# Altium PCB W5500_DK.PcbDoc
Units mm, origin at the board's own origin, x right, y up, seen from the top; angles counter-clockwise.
Board outline 152.4 x 101.6 mm, 2 copper layers (Top Layer, Bottom Layer); 6 components, 71 nets, 264 pads, 61 vias.
Unrouted connection lines stored in the file: 47.
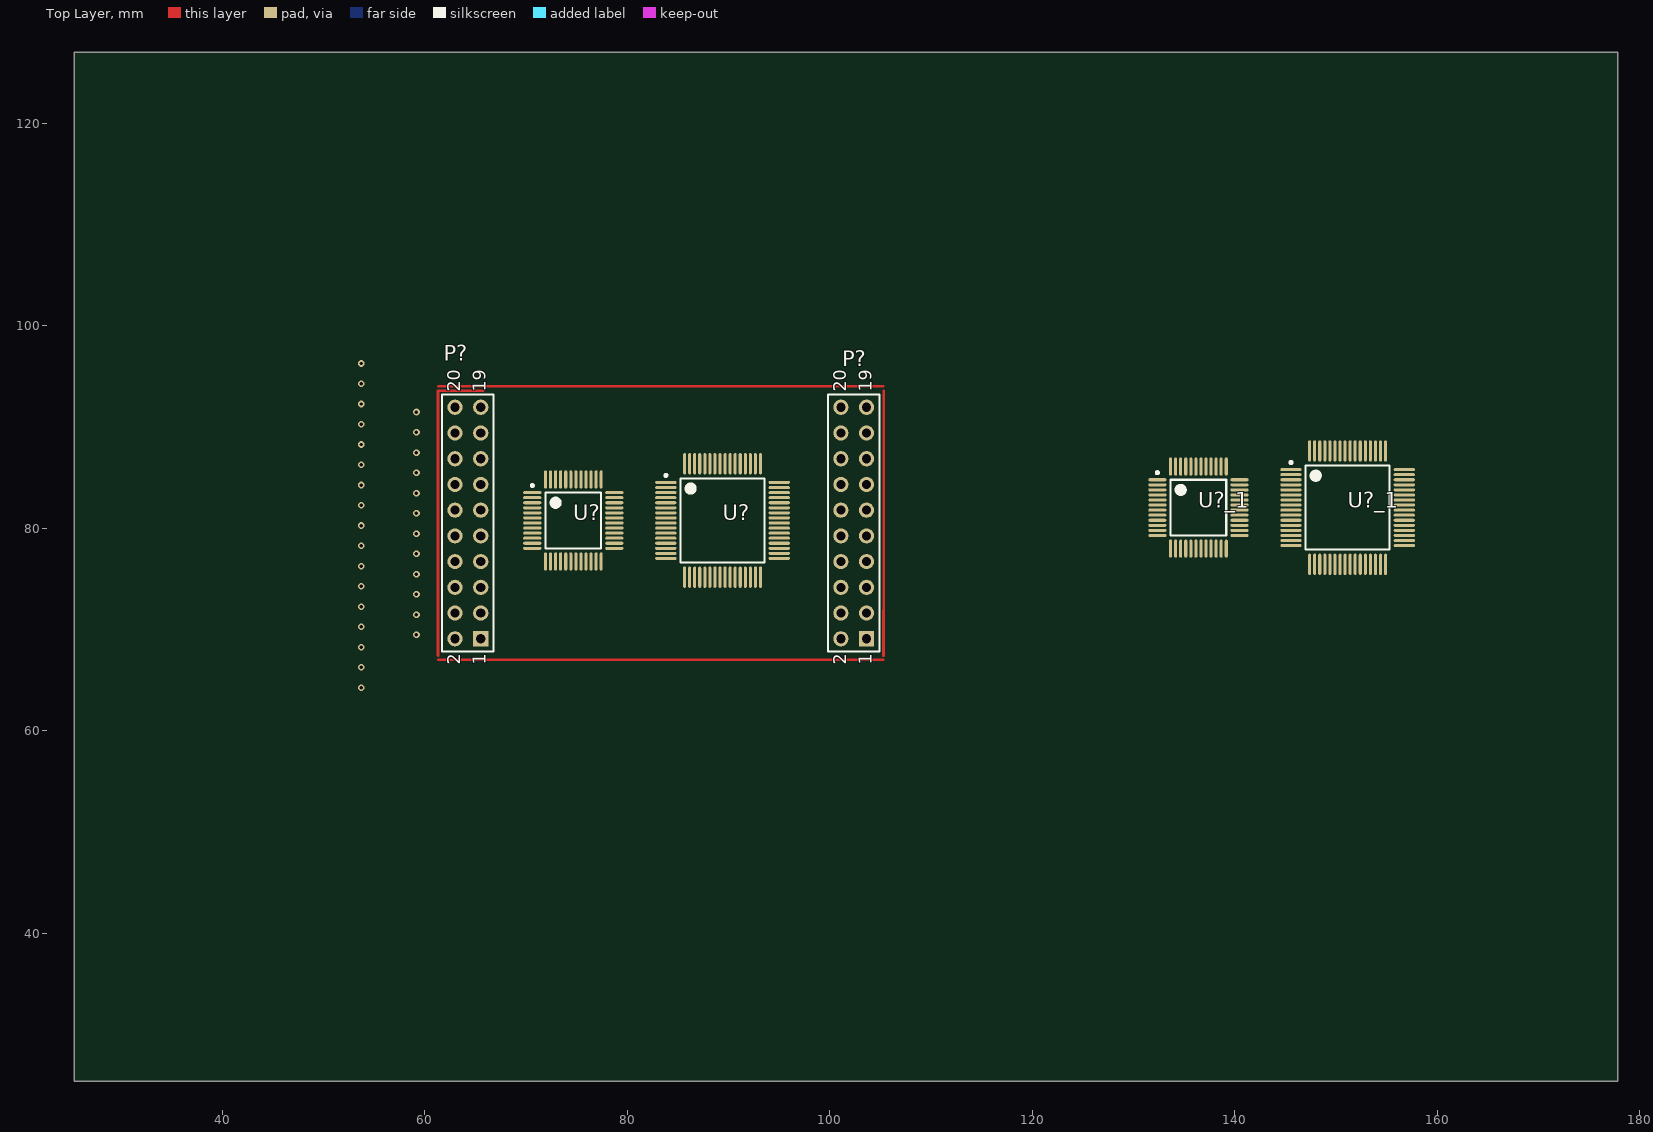
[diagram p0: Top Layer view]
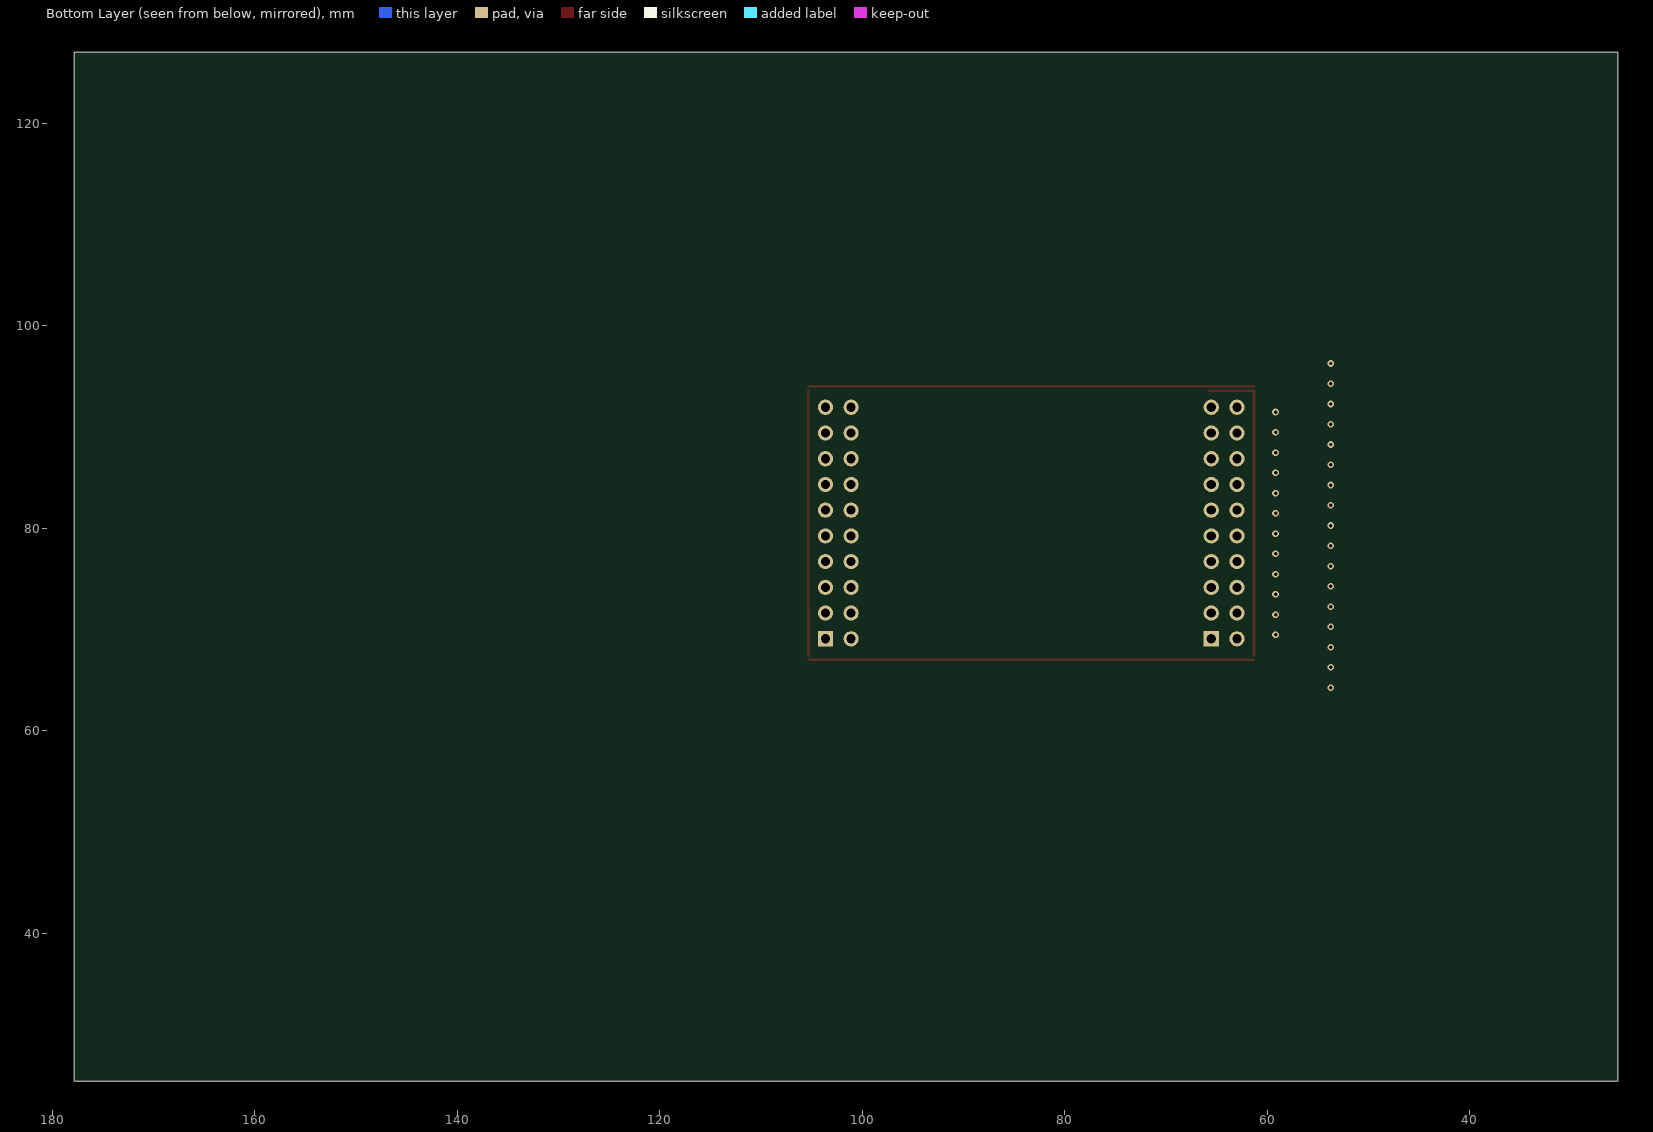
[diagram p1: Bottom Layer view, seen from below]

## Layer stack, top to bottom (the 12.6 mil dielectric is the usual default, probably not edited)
Top Layer: signal copper 0.0356
Dielectric: dielectric 0.32, FR-4, Dk 4.8
Bottom Layer: signal copper 0.0356

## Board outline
25.4,25.4 177.8,25.4 177.8,127 25.4,127

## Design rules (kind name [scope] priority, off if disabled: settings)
Clearance [All] p1: gap=0.254
PolygonConnect [All] p1: connectstyle=Relief reliefconductorwidth=0.254 reliefentries=4 polygonreliefangle="90 Angle"
RoutingVias [All] p1: holewidth=0.711 width=1.27 viastyle="Through Hole" minholewidth=0.711 minwidth=1.27 maxholewidth=0.711 maxwidth=1.27
SilkscreenOverComponentPads [All] p1: minsilkscreentomaskgap=0.254
SolderMaskExpansion [All] p1: expansion=0.102
TestPointUsage [All] p1: valid=0 allowmultiple=FALSE
Testpoint [All] p1: side=15 testpointundercomponent=TRUE minsize=1.016 maxsize=2.54 preferedsize=1.524 minholesize=0 maxholesize=1.016 preferedholesize=0.813 testpointgrid=0.025 style=1023 order=0-112345678
Width [All] p1: maxlimit=0.254 minlimit=0.254 preferedwidth=0.254
23 further rules are at their usual default settings.

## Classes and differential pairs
component class W5500+STM32: C? P? R? U? Y?

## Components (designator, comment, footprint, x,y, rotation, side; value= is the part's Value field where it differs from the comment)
P? "Header 10X2" HDR2X10 65.532,69.088 r90 top
P? "Header 10X2" HDR2X10 103.632,69.088 r90 top
U? "W5500" TQFP48_N 74.676,80.772 r0 top
U? "STM32F103RC" LQFP64_M 89.408,80.772 r0 top
U?_1 "STM32F103RC" LQFP64_M 151.13,82.042 r0 top (schematic designator U?)
U?_1 "W5500" TQFP48_N 136.398,82.042 r0 top (schematic designator U?)

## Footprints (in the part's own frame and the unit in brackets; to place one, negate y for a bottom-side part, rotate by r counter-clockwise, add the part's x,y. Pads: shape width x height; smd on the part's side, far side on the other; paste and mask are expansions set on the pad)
HDR2X10 [mm] "Connector; Header; 10x2 Position"
  rect 1.5x1.5 hole 0.9: 1(0,0)
  round 1.5 hole 0.9: 2(0,2.54) 3(2.54,0) 4(2.54,2.54) 5(5.08,0) 6(5.08,2.54) 7(7.62,0) 8(7.62,2.54) 9(10.16,0) 10(10.16,2.54) 11(12.7,0) 12(12.7,2.54) 13(15.24,0) 14(15.24,2.54) 15(17.78,0) 16(17.78,2.54) 17(20.32,0) 18(20.32,2.54) 19(22.86,0) 20(22.86,2.54)
  silkscreen extent -1.27,-1.27 24.13,3.81
LQFP64_M [mm] "Thin QFP, 64-Leads, Body 10x10mm, Pitch 0.5mm, IPC Low Density"
  oval 2.1x0.3 smd: 1(-5.6,3.75) 2(-5.6,3.25) 3(-5.6,2.75) 4(-5.6,2.25) 5(-5.6,1.75) 6(-5.6,1.25) 7(-5.6,0.75) 8(-5.6,0.25) 9(-5.6,-0.25) 10(-5.6,-0.75) 11(-5.6,-1.25) 12(-5.6,-1.75) 13(-5.6,-2.25) 14(-5.6,-2.75) 15(-5.6,-3.25) 16(-5.6,-3.75) 33(5.6,-3.75) 34(5.6,-3.25) 35(5.6,-2.75) 36(5.6,-2.25) 37(5.6,-1.75) 38(5.6,-1.25) 39(5.6,-0.75) 40(5.6,-0.25) 41(5.6,0.25) 42(5.6,0.75) 43(5.6,1.25) 44(5.6,1.75) 45(5.6,2.25) 46(5.6,2.75) 47(5.6,3.25) 48(5.6,3.75)
  oval 0.3x2.1 smd: 17(-3.75,-5.6) 18(-3.25,-5.6) 19(-2.75,-5.6) 20(-2.25,-5.6) 21(-1.75,-5.6) 22(-1.25,-5.6) 23(-0.75,-5.6) 24(-0.25,-5.6) 25(0.25,-5.6) 26(0.75,-5.6) 27(1.25,-5.6) 28(1.75,-5.6) 29(2.25,-5.6) 30(2.75,-5.6) 31(3.25,-5.6) 32(3.75,-5.6) 49(3.75,5.6) 50(3.25,5.6) 51(2.75,5.6) 52(2.25,5.6) 53(1.75,5.6) 54(1.25,5.6) 55(0.75,5.6) 56(0.25,5.6) 57(-0.25,5.6) 58(-0.75,5.6) 59(-1.25,5.6) 60(-1.75,5.6) 61(-2.25,5.6) 62(-2.75,5.6) 63(-3.25,5.6) 64(-3.75,5.6)
  silkscreen extent -5.72,-4.15 4.15,4.57, body extent -5,-5 5,5, height 1.6
TQFP48_N [mm] "Thin QFP, 48-Leads, Body 7x7mm, Pitch 0.5mm, IPC Medium Density"
  oval 1.8x0.3 smd: 1(-4.05,2.75) 2(-4.05,2.25) 3(-4.05,1.75) 4(-4.05,1.25) 5(-4.05,0.75) 6(-4.05,0.25) 7(-4.05,-0.25) 8(-4.05,-0.75) 9(-4.05,-1.25) 10(-4.05,-1.75) 11(-4.05,-2.25) 12(-4.05,-2.75) 25(4.05,-2.75) 26(4.05,-2.25) 27(4.05,-1.75) 28(4.05,-1.25) 29(4.05,-0.75) 30(4.05,-0.25) 31(4.05,0.25) 32(4.05,0.75) 33(4.05,1.25) 34(4.05,1.75) 35(4.05,2.25) 36(4.05,2.75)
  oval 0.3x1.8 smd: 13(-2.75,-4.05) 14(-2.25,-4.05) 15(-1.75,-4.05) 16(-1.25,-4.05) 17(-0.75,-4.05) 18(-0.25,-4.05) 19(0.25,-4.05) 20(0.75,-4.05) 21(1.25,-4.05) 22(1.75,-4.05) 23(2.25,-4.05) 24(2.75,-4.05) 37(2.75,4.05) 38(2.25,4.05) 39(1.75,4.05) 40(1.25,4.05) 41(0.75,4.05) 42(0.25,4.05) 43(-0.25,4.05) 44(-0.75,4.05) 45(-1.25,4.05) 46(-1.75,4.05) 47(-2.25,4.05) 48(-2.75,4.05)
  silkscreen extent -4.17,-2.75 2.75,3.57, body extent -3.5,-3.5 3.5,3.5, height 1.6

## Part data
P? P?: "Header, 10-Pin, Dual row"

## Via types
v1: diameter 0.66, hole 0.33, Top Layer to Bottom Layer, tented both sides, 61 vias

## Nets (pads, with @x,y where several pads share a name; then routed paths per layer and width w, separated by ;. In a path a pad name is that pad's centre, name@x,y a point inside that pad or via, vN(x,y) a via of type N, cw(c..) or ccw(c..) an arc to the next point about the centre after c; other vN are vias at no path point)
ACTLED: U?.27@78.726,79.022
BOOT0: 
DUPLED: U?.26@78.726,78.522
GND: U?.3@70.626,82.522 U?.9@70.626,79.522 U?.12@83.808,79.022 U?.14@72.426,76.722 U?.16@73.426,76.722 U?.18@86.158,75.172 U?.19@74.926,76.722 U?.29@78.726,80.022 U?.47@95.008,84.022 U?.48@71.926,84.822 U?.63
I2C_SCL: 
I2C_SDA: 
JTDI: U?.50
LINKLED: U?.25@78.726,78.022
NetC?_1: U?.30@78.726,80.522
NetC?_2: U?.20@75.426,76.722
NetR?_1: U?.10@70.626,79.022
NetR?_2: U?.31
NRESET: P?.16@62.992,86.868 U?.7@70.626,80.522
PA0: U?.14@83.808,78.022
PA1: 
PA2: U?.16@83.808,77.022
PA3: 
PA4: U?.20@87.158,75.172
PA5: 
PA6: U?.22@88.158,75.172
PA7: P?.5@65.532,74.168 U?.23@88.658,75.172
PA8: P?.14@62.992,84.328 U?.41@95.008,81.022
PA9: P?.12@62.992,81.788 U?.42@95.008,81.522
PA10: 
PA11: P?.8@62.992,76.708
PA12: P?.6@62.992,74.168
PA13: U?.46@95.008,83.522
PA14: U?.49
PB2/BOOT1: U?.28@78.726,79.522
PB8: U?.61
PB9: U?.62
PB10: U?.29@91.658,75.172
PB11: U?.30@92.158,75.172
PC0: 
PC1: U?.9@83.808,80.522
PC2: U?.10@83.808,80.022
PC3: 
PC4: 
PC5: P?.9@65.532,79.248 U?.25@89.658,75.172
PC7: U?.38@95.008,79.522
PC8: U?.39@95.008,80.022
PC9: U?.40@95.008,80.522
PC10: U?.51
PC11: P?.18@62.992,89.408 U?.52
PC12: U?.53
PC13: P?.13@65.532,84.328
PC14: P?.15@65.532,86.868 U?.3@83.808,83.522
PC15: P?.17@65.532,89.408
PD2: P?.11@65.532,81.788 U?.54
PD3: U?.55
PD4: U?.56
PD5: U?.57
RXN: P?.2@62.992,69.088 U?.5@83.808,82.522
RXP: P?.4@62.992,71.628 U?.6@83.808,82.022
SPDLED: U?.24
TXN: P?.1@65.532,69.088 U?.1@70.626,83.522
TXP: P?.3@65.532,71.628 U?.2
VBAT: U?.1@83.808,84.522
VCC: P?.19@65.532,91.948 P?.20@62.992,91.948 U?.13@83.808,78.522 U?.19@86.658,75.172 U?.28@91.158,75.172 U?.32@93.158,75.172 U?.48@95.008,84.522 U?.64
VCCA: P?.7@65.532,76.708 U?.4 U?.8 U?.11 U?.15 U?.17 U?.21
W5500_INTN: U?.37@77.426,84.822
W5500_MISO: 
W5500_MOSI: U?.35@78.726,83.022 U?.36@78.726,83.522
W5500_PMODE0: U?.45@73.426,84.822
W5500_PMODE1: U?.44@73.926,84.822
W5500_PMODE2: U?.43@74.426,84.822
W5500_RST: P?.10@62.992,79.248 U?.37@95.008,79.022
W5500_SCLK: U?.34@78.726,82.522
W5500_SCSN: U?.32@78.726,81.522 U?.33@78.726,82.022
XTAL_N: U?.6@70.626,81.022
XTAL_P: U?.5@70.626,81.522
pads on no net: P?.1@103.632,69.088 P?.2@101.092,69.088 P?.3@103.632,71.628 P?.4@101.092,71.628 P?.5@103.632,74.168 P?.6@101.092,74.168 P?.7@103.632,76.708 P?.8@101.092,76.708 P?.9@103.632,79.248 P?.10@101.092,79.248 P?.11@103.632,81.788 P?.12@101.092,81.788 P?.13@103.632,84.328 P?.14@101.092,84.328 P?.15@103.632,86.868 P?.16@101.092,86.868 P?.17@103.632,89.408 P?.18@101.092,89.408 P?.19@103.632,91.948 P?.20@101.092,91.948 U?.7@83.808,81.522 U?.12@70.626,78.022 U?.13@71.926,76.722 U?.18@74.426,76.722 U?.22@76.426,76.722 U?.23@76.926,76.722 U?.26@90.158,75.172 U?.27@90.658,75.172 U?.33@95.008,77.022 U?.34@95.008,77.522 U?.35@95.008,78.022 U?.36@95.008,78.522 U?.38@76.926,84.822 U?.39@76.426,84.822 U?.40@75.926,84.822 U?.41@75.426,84.822 U?.42@74.926,84.822 U?.43@95.008,82.022 U?.44@95.008,82.522 U?.45@95.008,83.022 U?.46@72.926,84.822 U?.47@72.426,84.822 U?.58 U?.59 U?.60 U?_1.1 U?_1.2 U?_1.3 U?_1.4 U?_1.5 U?_1.6 U?_1.7 U?_1.8 U?_1.9 U?_1.10 U?_1.11 U?_1.12 U?_1.13 U?_1.14 U?_1.15 U?_1.16 U?_1.17 U?_1.18 U?_1.19 U?_1.20 U?_1.21 U?_1.22 U?_1.23 U?_1.24 U?_1.25 U?_1.26 U?_1.27 U?_1.28 U?_1.29 U?_1.30 U?_1.31 U?_1.32 U?_1.33 U?_1.34 U?_1.35 U?_1.36 U?_1.37 U?_1.38 U?_1.39 U?_1.40 U?_1.41 U?_1.42 U?_1.43 U?_1.44 U?_1.45 U?_1.46 U?_1.47 U?_1.48 U?_1.49 U?_1.50 U?_1.51 U?_1.52 U?_1.53 U?_1.54 U?_1.55 U?_1.56 U?_1.57 U?_1.58 U?_1.59 U?_1.60 U?_1.61 U?_1.62 U?_1.63 U?_1.64
copper on no net: | length 153.5
  Top Layer w0.254: 61.311,67.437 61.311,93.599 ; 61.341,67.017 105.283,67.017 ; 61.341,67.437 61.341,71.882 ; 61.341,93.599 65.786,93.599 ; 61.341,94.019 105.283,94.019 ; 105.283,67.437 105.283,71.882 ; 105.313,67.437 105.313,93.599
  other v1: 53.721,64.266 53.721,66.266 53.721,66.266 53.721,68.266 53.721,68.266 103.632,69.088 59.182,69.473 53.721,70.266 53.721,70.266 59.182,71.473 59.182,71.473 53.721,72.266 53.721,72.266 59.182,73.473 59.182,73.473 53.721,74.266 53.721,74.266 59.182,75.473 59.182,75.473 53.721,76.266 53.721,76.266 59.182,77.473 59.182,77.473 53.721,78.266 53.721,78.266 59.182,79.473 59.182,79.473 53.721,80.266 53.721,80.266 59.182,81.473 59.182,81.473 53.721,82.266 53.721,82.266 59.182,83.473 59.182,83.473 53.721,84.266 53.721,84.266 59.182,85.473 59.182,85.473 53.721,86.266 53.721,86.266 59.182,87.473 59.182,87.473 53.721,88.266 53.721,88.266 59.182,89.473 59.182,89.473 53.721,90.266 53.721,90.266 59.182,91.473 59.182,91.473 62.992,91.948 62.992,91.948 103.632,91.948 103.632,91.948 103.632,91.948 53.721,92.266 53.721,92.266 53.721,94.266 53.721,94.266 53.721,96.266

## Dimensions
105.283,94.019 to 105.283,67.017 on Top Layer
105.313,93.599 to 61.311,93.599 on Top Layer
